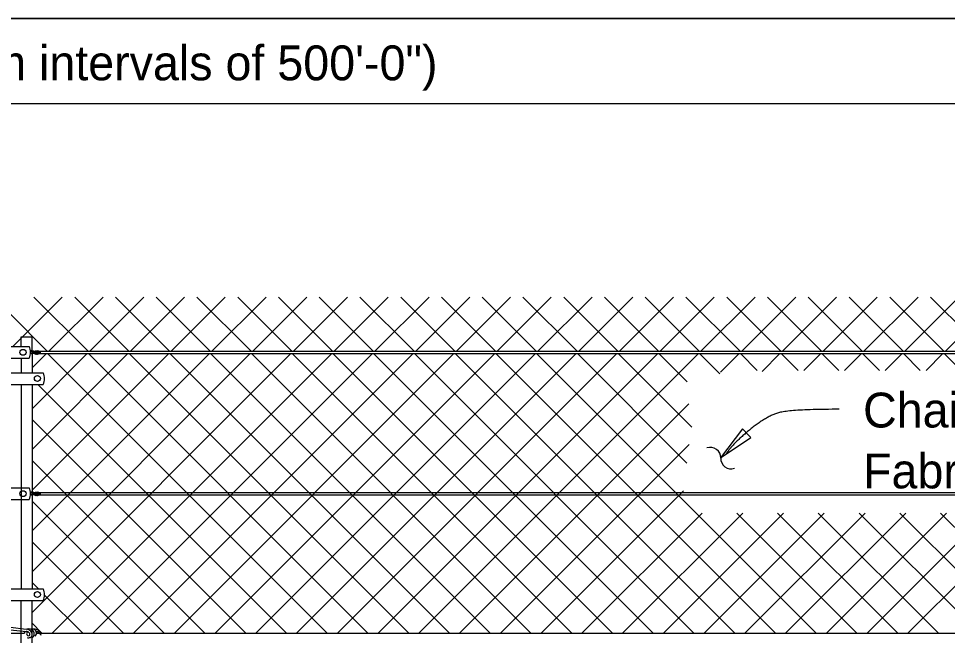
# Model space of a CAD drawing. Extents: x 0 to 41.2, y 0 to 26.
# Drawn here: x 12.4 to 17.77, y 22.39 to 25.96 of the extents above; entities that cross this region are included whole.
import ezdxf

# ---------------------------------------------------------------- set-up
doc = ezdxf.new("R2010")
doc.units = 0
for name, color, linetype in [('ActivePts-ConstElements', 7, 'Continuous'), ('Dimension', 7, 'Continuous'), ('Miscellaneous', 7, 'Continuous'), ('Miscellaneous1', 7, 'Continuous'), ('SteelMisc', 7, 'Continuous'), ('TextStructures', 7, 'Continuous')]:
    doc.layers.add(name, color=color, linetype=linetype)

msp = doc.modelspace()

# ---------------------------------------------------------------- linework, layer by layer
at = {"layer": 'ActivePts-ConstElements'}
msp.add_lwpolyline([(0, 0), (41.2106, 0), (41.2106, 25.96), (0, 25.96)], close=True, dxfattribs=at)
at = {"layer": 'Dimension'}
msp.add_line((2.2062, 25.4682), (22.2062, 25.4682), dxfattribs=at)
msp.add_lwpolyline([(16.4595, 23.4182), (16.6347, 23.5361), (16.5861, 23.5872)], close=True, dxfattribs=at)
for centre, start, end in [((16.4004, 23.4201), 357.7178, 109.445), ((16.5195, 23.4153), 177.7178, 289.445)]:
    msp.add_arc(centre, 0.0596, start, end, dxfattribs=at)
msp.add_open_spline([(17.1447, 23.6998), (16.8545, 23.6998), (16.7179, 23.655), (16.5309, 23.5014), (16.4925, 23.4438)], degree=2, dxfattribs=at)
at = {"layer": 'Miscellaneous'}
for p, q in [((12.3656, 24.0631), (12.6516, 24.349)), ((12.4881, 24.349), (12.8006, 24.0365)), ((12.5748, 24.0365), (12.8873, 24.349)), ((12.7238, 24.349), (13.0364, 24.0365)), ((12.8105, 24.0365), (13.123, 24.349)), ((12.9595, 24.349), (13.2721, 24.0365)), ((13.0462, 24.0365), (13.3587, 24.349)), ((13.1952, 24.349), (13.5078, 24.0365)), ((13.2819, 24.0365), (13.5944, 24.349)), ((13.4309, 24.349), (13.7435, 24.0365)), ((13.5176, 24.0365), (13.8301, 24.349)), ((13.6666, 24.349), (13.9792, 24.0365)), ((13.7533, 24.0365), (14.0658, 24.349)), ((13.9023, 24.349), (14.2149, 24.0365)), ((13.989, 24.0365), (14.3015, 24.349)), ((14.138, 24.349), (14.4506, 24.0365)), ((14.2247, 24.0365), (14.5372, 24.349)), ((14.3737, 24.349), (14.6863, 24.0365)), ((14.4604, 24.0365), (14.7729, 24.349)), ((14.6094, 24.349), (14.922, 24.0365)), ((14.6961, 24.0365), (15.0086, 24.349)), ((14.8451, 24.349), (15.1577, 24.0365)), ((14.9318, 24.0365), (15.2443, 24.349)), ((15.0808, 24.349), (15.3934, 24.0365)), ((15.1675, 24.0365), (15.48, 24.349)), ((15.3165, 24.349), (15.6291, 24.0365)), ((15.4032, 24.0365), (15.7157, 24.349)), ((15.5522, 24.349), (15.8648, 24.0365)), ((15.6389, 24.0365), (15.9514, 24.349)), ((15.7879, 24.349), (16.1005, 24.0365)), ((15.8746, 24.0365), (16.1871, 24.349)), ((16.0236, 24.349), (16.3362, 24.0365)), ((16.1103, 24.0365), (16.4228, 24.349)), ((16.2593, 24.349), (16.5719, 24.0365)), ((16.346, 24.0365), (16.6585, 24.349)), ((16.4951, 24.349), (16.8076, 24.0365)), ((16.5817, 24.0365), (16.8942, 24.349)), ((16.7308, 24.349), (17.0433, 24.0365)), ((16.8174, 24.0365), (17.1299, 24.349)), ((16.9665, 24.349), (17.279, 24.0365)), ((17.0531, 24.0365), (17.3656, 24.349)), ((17.2022, 24.349), (17.5147, 24.0365)), ((17.2888, 24.0365), (17.6013, 24.349)), ((17.4379, 24.349), (17.7504, 24.0365)), ((17.5245, 24.0365), (17.837, 24.349)), ((17.6736, 24.349), (17.9861, 24.0365)), ((17.7602, 24.0365), (18.0727, 24.349)), ((12.352, 24.2494), (12.5649, 24.0365)), ((12.4771, 22.5246), (13.9742, 24.0218)), ((12.4771, 22.7603), (13.7385, 24.0218)), ((12.4771, 22.996), (13.5028, 24.0218)), ((12.4771, 23.2317), (13.2671, 24.0218)), ((12.4771, 23.4674), (13.0314, 24.0218)), ((12.4771, 23.7031), (12.7957, 24.0218)), ((12.4771, 23.9388), (12.56, 24.0218)), ((12.5669, 24.0218), (14.1839, 22.4048)), ((12.5929, 22.4048), (14.2099, 24.0218)), ((12.8026, 24.0218), (14.4196, 22.4048)), ((12.8286, 22.4048), (14.4456, 24.0218)), ((13.0383, 24.0218), (14.6553, 22.4048)), ((13.0643, 22.4048), (14.6813, 24.0218)), ((13.274, 24.0218), (14.891, 22.4048)), ((13.3, 22.4048), (14.917, 24.0218)), ((13.5097, 24.0218), (15.1267, 22.4048)), ((13.5357, 22.4048), (15.1527, 24.0218)), ((13.7454, 24.0218), (15.3624, 22.4048)), ((13.7714, 22.4048), (15.3884, 24.0218)), ((13.9811, 24.0218), (15.5981, 22.4048)), ((14.0071, 22.4048), (15.6241, 24.0218)), ((14.2168, 24.0218), (15.8338, 22.4048)), ((14.2428, 22.4048), (15.8598, 24.0218)), ((14.4525, 24.0218), (16.0695, 22.4048)), ((14.4785, 22.4048), (16.0955, 24.0218)), ((14.6882, 24.0218), (16.3052, 22.4048)), ((14.7142, 22.4048), (16.3312, 24.0218)), ((14.9239, 24.0218), (16.5409, 22.4048)), ((15.1596, 24.0218), (16.2441, 22.9373)), ((15.3953, 24.0218), (16.2441, 23.173)), ((15.631, 24.0218), (16.2647, 23.3881)), ((15.8667, 24.0218), (16.293, 23.5955)), ((16.1024, 24.0218), (16.2656, 23.8586)), ((16.3381, 24.0218), (16.4551, 23.9048)), ((16.4597, 23.9145), (16.5669, 24.0218)), ((16.5738, 24.0218), (16.6715, 23.9241)), ((16.699, 23.9181), (16.8026, 24.0218)), ((16.8095, 24.0218), (16.9072, 23.9241)), ((16.9407, 23.9241), (17.0384, 24.0218)), ((17.0452, 24.0218), (17.1429, 23.9241)), ((17.1764, 23.9241), (17.2741, 24.0218)), ((17.281, 24.0218), (17.3786, 23.9241)), ((17.4121, 23.9241), (17.5098, 24.0218)), ((17.5167, 24.0218), (17.6143, 23.9241)), ((17.6478, 23.9241), (17.7455, 24.0218)), ((17.7524, 24.0218), (17.85, 23.9241)), ((12.5096, 23.8433), (13.9482, 22.4048)), ((14.9499, 22.4048), (16.2763, 23.7311)), ((12.4771, 23.6402), (13.7125, 22.4048)), ((15.1856, 22.4048), (16.2774, 23.4965)), ((12.4771, 23.4045), (13.4768, 22.4048)), ((15.4214, 22.4048), (16.2441, 23.2275)), ((12.4771, 23.1688), (13.2411, 22.4048)), ((16.2441, 23.173), (17.0123, 22.4048)), ((15.6571, 22.4048), (16.3522, 23.0999)), ((15.8928, 22.4048), (16.5879, 23.0999)), ((16.1285, 22.4048), (16.8236, 23.0999)), ((16.3642, 22.4048), (17.0593, 23.0999)), ((16.5529, 23.0999), (17.248, 22.4048)), ((16.5999, 22.4048), (17.295, 23.0999)), ((16.7886, 23.0999), (17.4837, 22.4048)), ((16.8356, 22.4048), (17.5307, 23.0999)), ((17.0243, 23.0999), (17.7194, 22.4048)), ((17.0713, 22.4048), (17.7664, 23.0999)), ((17.26, 23.0999), (17.9551, 22.4048)), ((17.307, 22.4048), (18.0021, 23.0999)), ((17.4957, 23.0999), (18.1908, 22.4048)), ((17.5427, 22.4048), (18.2378, 23.0999)), ((17.7314, 23.0999), (18.4265, 22.4048)), ((12.4771, 22.9331), (13.0054, 22.4048)), ((16.2441, 22.9373), (16.7766, 22.4048)), ((12.4771, 22.6974), (12.5135, 22.6609)), ((12.5496, 22.6249), (12.7697, 22.4048)), ((12.4771, 22.4617), (12.534, 22.4048))]:
    msp.add_line(p, q, dxfattribs=at)
at = {"layer": 'Miscellaneous1'}
msp.add_lwpolyline([(0, 25.96), (41.2106, 25.96), (41.2106, 0), (0, 0)], close=True, dxfattribs=at)
at = {"layer": 'SteelMisc'}
for p, q in [((12.4145, 24.0636), (12.4145, 24.1198)), ((12.4145, 24.1198), (12.477, 24.1198)), ((12.477, 24.0396), (12.477, 24.1198)), ((12.0505, 24.0637), (12.4602, 24.0637)), ((12.4675, 24.0412), (12.4967, 24.0366)), ((12.4676, 24.0412), (12.4968, 24.0366)), ((12.468, 24.0207), (12.5016, 24.0264)), ((12.4681, 24.0362), (12.4941, 24.0321)), ((12.4681, 24.0207), (12.5017, 24.0264)), ((12.4682, 24.0362), (12.4942, 24.0321)), ((12.4684, 24.0255), (12.4983, 24.0304)), ((12.4685, 24.0255), (12.4984, 24.0304)), ((12.477, 24.0347), (12.477, 24.0269)), ((12.4771, 24.0396), (12.4771, 23.9109)), ((12.5051, 24.0365), (21.8852, 24.0365)), ((12.5051, 24.0218), (21.9118, 24.0218)), ((12.0505, 23.9959), (12.4598, 23.9959)), ((12.4146, 23.9959), (12.4146, 23.9109)), ((12.0505, 23.9109), (12.5416, 23.9109)), ((12.0505, 23.8433), (12.5408, 23.8433)), ((12.4146, 23.8433), (12.4146, 22.6609)), ((12.4771, 23.8433), (12.4771, 22.6609)), ((12.0506, 23.2462), (12.4603, 23.2462)), ((12.4676, 23.2237), (12.4969, 23.2191)), ((12.4677, 23.2237), (12.497, 23.2191)), ((12.4683, 23.2187), (12.4943, 23.2146)), ((12.4684, 23.2187), (12.4944, 23.2146)), ((12.4686, 23.2081), (12.4985, 23.213)), ((12.4687, 23.2081), (12.4986, 23.213)), ((12.4772, 23.2172), (12.4772, 23.2094)), ((12.5053, 23.219), (21.8854, 23.219)), ((12.0506, 23.1785), (12.46, 23.1785)), ((12.4681, 23.2033), (12.5018, 23.2089)), ((12.4683, 23.2033), (12.5019, 23.2089)), ((12.5053, 23.2043), (21.912, 23.2043)), ((12.0505, 22.6609), (12.5416, 22.6609)), ((12.0505, 22.5933), (12.5408, 22.5933)), ((12.4146, 21.4109), (12.4146, 22.5933)), ((12.4771, 21.4109), (12.4771, 22.5933)), ((12.3515, 22.4391), (12.4435, 22.4275)), ((12.3515, 22.4245), (12.4434, 22.415)), ((12.352, 22.4048), (12.4324, 22.4048)), ((12.5028, 22.4048), (12.518, 22.4048)), ((12.5265, 22.4048), (21.8852, 22.4048))]:
    msp.add_line(p, q, dxfattribs=at)
for centre, major_axis in [((12.4241, 24.0291), (-0.0178, 0)), ((12.5079, 23.8782), (-0.0177, 0)), ((12.4243, 23.2117), (-0.0178, 0)), ((12.5079, 22.6282), (-0.0177, 0))]:
    msp.add_ellipse(centre, major_axis=major_axis, ratio=0.957868, dxfattribs=at)
for centre, major_axis, ratio, start_param, end_param in [((12.3908, 24.03), (0.0776, 0), 0.957868, 5.803915, 6.752041), ((12.4993, 24.0267), (-0.0095, 0), 0.957868, 5.673972, 6.052579), ((12.4993, 24.0267), (-0.0095, 0), 0.957868, 0.252467, 1.271421), ((12.4934, 24.0225), (0.00982, 0), 0.957868, 0.655696, 1.505671), ((12.4953, 24.0274), (0.0115, -0.0041), 0.737732, 5.08821, 8.212701), ((12.4987, 24.025), (0.00301, 0), 0.957868, 3.28349, 5.170635), ((12.4993, 24.0272), (-0.00453, 0), 0.957868, 5.149727, 5.551998), ((12.4966, 24.0259), (0.00527, 0), 0.957868, 5.058829, 7.342751), ((12.501, 24.0283), (-0.00872, 0), 0.957868, 2.1008, 4.992926), ((12.4987, 24.025), (0.00301, 0), 0.957868, 0.004594, 0.141897), ((12.5071, 24.0278), (0.00944, 0), 0.957868, 4.316497, 6.557353), ((12.5075, 24.0288), (-0.00872, 0), 0.957868, 3.323334, 4.992926), ((12.5075, 24.0288), (-0.00503, 0), 0.92697, 1.780895, 4.712389), ((12.5122, 24.0233), (-0.0142, 0), 0.957868, 3.141593, 4.79635), ((12.5042, 24.0082), (0.0274, 0), 0.957868, 0.628521, 1.149654), ((12.472, 23.8778), (0.0776, 0), 0.957868, 5.801244, 6.745158), ((12.391, 23.2125), (0.0776, 0), 0.957868, 5.803915, 6.752041), ((12.4994, 23.2092), (-0.0095, 0), 0.957868, 5.673972, 6.052579), ((12.4936, 23.205), (0.00982, 0), 0.957868, 0.655696, 1.505671), ((12.4955, 23.2099), (0.0115, -0.0041), 0.737732, 5.08821, 8.212701), ((12.4995, 23.2097), (-0.00453, 0), 0.957868, 5.149727, 5.551998), ((12.4967, 23.2084), (0.00527, 0), 0.957868, 5.058829, 7.342751), ((12.5011, 23.2108), (-0.00872, 0), 0.957868, 2.1008, 4.992926), ((12.5073, 23.2104), (0.00944, 0), 0.957868, 4.316497, 6.557353), ((12.5077, 23.2113), (-0.00872, 0), 0.957868, 3.323334, 4.992926), ((12.5077, 23.2113), (-0.00503, 0), 0.92697, 1.780895, 4.712389), ((12.5124, 23.2058), (-0.0142, 0), 0.957868, 3.141593, 4.79635), ((12.5044, 23.1908), (0.0274, 0), 0.957868, 0.628521, 1.149654), ((12.4994, 23.2092), (-0.0095, 0), 0.957868, 0.252467, 1.271421), ((12.4989, 23.2075), (0.00301, 0), 0.957868, 3.28349, 5.170635), ((12.4989, 23.2075), (0.00301, 0), 0.957868, 0.004594, 0.141897), ((12.472, 22.6278), (0.0776, 0), 0.957868, 5.801244, 6.745158), ((12.4572, 22.4013), (-0.0251, 0), 0.957868, 5.640694, 6.136824), ((12.4417, 22.3902), (0.0259, 0), 0.957868, 0.636815, 1.505671), ((12.4468, 22.4032), (0.0303, -0.0108), 0.724765, 0.058937, 1.929515), ((12.4574, 22.4025), (-0.0119, 0), 0.957868, 5.149694, 6.840495), ((12.4603, 22.4014), (-0.0295, 0), 0.957868, 2.287002, 5.15055), ((12.4501, 22.3991), (0.0139, 0), 0.957868, 6.080589, 6.743456), ((12.479, 22.4067), (-0.023, 0), 0.957868, 3.422131, 5.0491), ((12.4915, 22.3923), (-0.0373, 0), 0.957868, 3.175144, 4.855322), ((12.4779, 22.4042), (0.0249, 0), 0.957868, 5.476514, 6.65252), ((12.4704, 22.3526), (0.0724, 0), 0.957868, 0.631079, 1.150052), ((12.4574, 22.4025), (-0.0119, 0), 0.957868, 0.560069, 0.643501), ((12.4558, 22.3967), (0.00795, 0), 0.957868, 3.283494, 6.243757), ((12.4569, 22.3945), (-0.0206, -0.0021), 0.798607, 1.063032, 2.96375)]:
    msp.add_ellipse(centre, major_axis=major_axis, ratio=ratio, start_param=start_param, end_param=end_param, dxfattribs=at)

# ---------------------------------------------------------------- texts
at = {"layer": 'Dimension'}
for s, p in [('Chain Link ', (17.2835, 23.5945)), ('Fabric ', (17.2835, 23.2425))]:
    msp.add_text(s, height=0.2016, dxfattribs=at).set_placement(p)
at = {"layer": 'TextStructures'}
msp.add_text('Pull Post Assembly (required at maximum intervals of 500\'-0")', height=0.2016, dxfattribs=at).set_placement((7.4383, 25.603))

doc.saveas('drawing.dxf')
